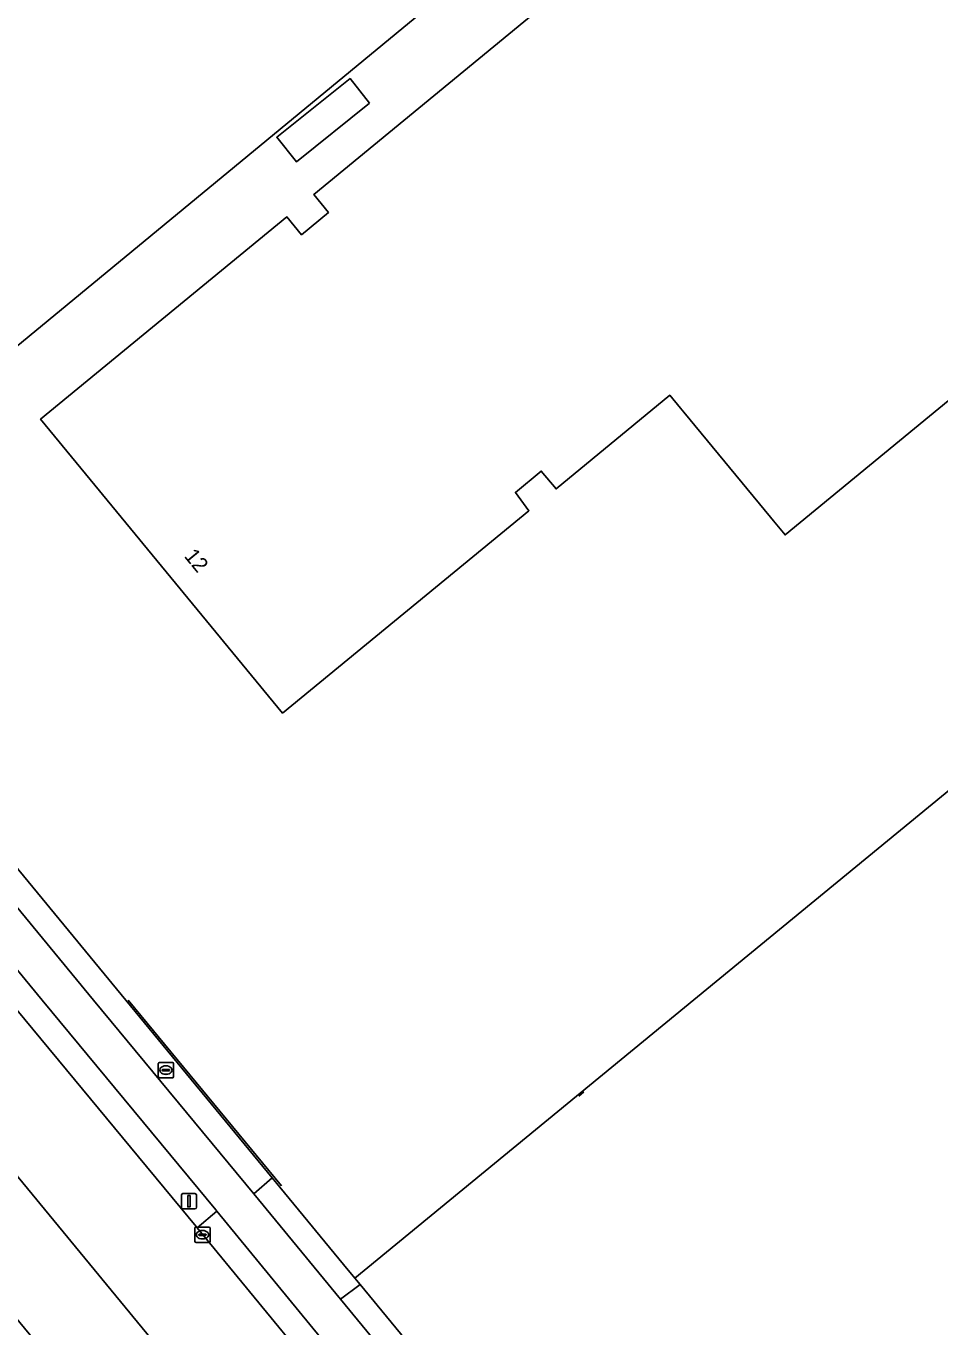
# Model space of a CAD drawing. Extents: x 156141 to 158132, y 385651 to 388333.
# Drawn here: x 157027.5 to 157087.7, y 386478.5 to 386564.1 of the extents above; entities that cross this region are included whole.
import ezdxf

# ---------------------------------------------------------------- set-up
doc = ezdxf.new("R2010")
doc.units = 0
for name, color, linetype in [('IMGEO_Berm_groen', 7, 'Continuous'), ('IMGEO_Brandkraan', 7, 'Continuous'), ('IMGEO_Erf', 7, 'Continuous'), ('IMGEO_Fietspad_gesloten', 7, 'Continuous'), ('IMGEO_Hek', 7, 'Continuous'), ('IMGEO_Kolk', 7, 'Continuous'), ('IMGEO_Lichtmast', 7, 'Continuous'), ('IMGEO_Pand', 7, 'Continuous'), ('IMGEO_Pand_nummerreeks', 7, 'Continuous'), ('IMGEO_Rijbaan_lokaal_gesloten', 7, 'Continuous'), ('IMGEO_Rijbaan_lokaal_open', 7, 'Continuous'), ('IMGEO_Voetpad_open', 7, 'Continuous')]:
    doc.layers.add(name, color=color, linetype=linetype)

msp = doc.modelspace()

# ---------------------------------------------------------------- linework, layer by layer
at = {"layer": 'IMGEO_Berm_groen'}
msp.add_lwpolyline([(157002.795, 386531.336), (157002.547, 386528.981), (157026.409, 386500), (157038.728, 386485.081), (157038.798, 386484.996), (157040.105, 386486.102), (157040.037, 386486.185), (157028.597, 386500)], close=True, dxfattribs=at)
msp.add_lwpolyline([(157002.333, 386508.861), (157009.629, 386500), (157103.143, 386386.435), (157105.1, 386384.051), (157109.728, 386387.854), (157107.759, 386390.255), (157017.392, 386500)], dxfattribs=at)
at = {"layer": 'IMGEO_Brandkraan'}
for p, q in [((157036.246, 386494.961), (157036.246, 386495.813)), ((157036.321, 386495.887), (157037.173, 386495.887)), ((157036.505, 386495.381), (157036.505, 386495.393)), ((157036.943, 386495.344), (157036.545, 386495.344)), ((157036.548, 386495.43), (157036.946, 386495.43)), ((157036.734, 386495.667), (157036.759, 386495.667)), ((157036.989, 386495.393), (157036.989, 386495.381)), ((157037.247, 386495.813), (157037.247, 386494.961)), ((157037.173, 386494.887), (157036.321, 386494.887)), ((157036.757, 386495.107), (157036.732, 386495.107))]:
    msp.add_line(p, q, dxfattribs=at)
for points in [[(157036.246, 386494.961), (157036.246, 386495.813)], [(157036.321, 386495.887), (157037.173, 386495.887)], [(157037.247, 386495.813), (157037.247, 386494.961)], [(157037.173, 386494.887), (157036.321, 386494.887)]]:
    msp.add_lwpolyline(points, dxfattribs=at)
for centre, radius, start, end in [((157036.323, 386495.811), 0.0765, 91.55205, 178.44795), ((157036.323, 386495.811), 0.0765, 91.55205, 178.44795), ((157036.545, 386495.39), 0.0403, 85.87752, 175.75265), ((157036.542, 386495.38), 0.0366, 178.93798, 274.71019), ((157036.946, 386495.387), 0.043, 264.86636, 352.45326), ((157036.95, 386495.392), 0.0386, 1.73085, 96.63898), ((157037.171, 386495.811), 0.0765, 1.55205, 88.44795), ((157037.171, 386495.811), 0.0765, 1.55205, 88.44795), ((157036.323, 386494.963), 0.0765, 181.55205, 268.44795), ((157036.323, 386494.963), 0.0765, 181.55205, 268.44795), ((157037.171, 386494.963), 0.0765, 271.55205, 358.44795), ((157037.171, 386494.963), 0.0765, 271.55205, 358.44795)]:
    msp.add_arc(centre, radius, start, end, dxfattribs=at)
for centre, major_axis, ratio, start_param, end_param in [((157036.733, 386495.387), (-0.387, 0.002), 0.722429, 4.712389, 7.853982), ((157036.758, 386495.387), (-0.39, 0.002), 0.717154, 1.570796, 4.712389)]:
    msp.add_ellipse(centre, major_axis=major_axis, ratio=ratio, start_param=start_param, end_param=end_param, dxfattribs=at)
at = {"layer": 'IMGEO_Erf'}
for points in [[(156920.91, 386652.293), (156913.636, 386646.333), (156919.699, 386638.931), (156919.907, 386638.664), (156922.955, 386634.963), (156962.332, 386587.153), (156969.416, 386578.552), (156982.109, 386563.141), (156988.377, 386555.544), (157000, 386541.408), (157034.096, 386500), (157043.743, 386488.284), (157044.247, 386487.672), (157048.737, 386482.212), (157049.528, 386481.275), (157107.842, 386410.438)], [(157151.722, 386565.874), (157139.123, 386581.228), (157135.47, 386578.262), (157123.976, 386568.812), (157130.529, 386560.852), (157115.807, 386548.732), (157109.245, 386556.702), (157077.524, 386530.624), (157076.749, 386531.562), (157076.55, 386531.804), (157070.842, 386538.714), (157070.635, 386538.981), (157069.927, 386539.821), (157062.44, 386533.651), (157061.467, 386534.832), (157059.761, 386533.43), (157060.649, 386532.218), (157044.427, 386518.897), (157028.492, 386538.247), (157044.713, 386551.57), (157045.678, 386550.395), (157047.448, 386551.867), (157046.482, 386553.041), (157111.922, 386606.864)]]:
    msp.add_lwpolyline(points, dxfattribs=at)
msp.add_lwpolyline([(157050.16, 386559.061), (157045.341, 386555.2), (157044.05, 386556.812), (157048.869, 386560.672)], close=True, dxfattribs=at)
at = {"layer": 'IMGEO_Fietspad_gesloten'}
for points in [[(156987.042, 386550.468), (156995.781, 386539.855), (157000, 386534.731), (157002.795, 386531.336), (157028.597, 386500), (157040.037, 386486.185), (157040.105, 386486.102), (157047.634, 386476.932), (157047.712, 386476.837), (157104.914, 386407.314)], [(157106.117, 386409.97), (157048.253, 386480.295), (157042.536, 386487.235), (157031.987, 386500), (157000, 386538.848)]]:
    msp.add_lwpolyline(points, dxfattribs=at)
at = {"layer": 'IMGEO_Hek'}
for points in [[(157112.507, 386613.649), (157010.32, 386529.349)], [(157151.722, 386565.874), (157049.177, 386481.677)], [(157044.352, 386487.757), (157034.269, 386500)], [(157064.266, 386493.954), (157063.939, 386493.68)]]:
    msp.add_lwpolyline(points, dxfattribs=at)
at = {"layer": 'IMGEO_Kolk'}
for p, q in [((157038.654, 386484.119), (157038.654, 386484.971)), ((157038.729, 386485.045), (157039.581, 386485.045)), ((157038.913, 386484.539), (157038.913, 386484.551)), ((157039.351, 386484.502), (157038.953, 386484.502)), ((157038.956, 386484.588), (157039.354, 386484.588)), ((157039.165, 386484.265), (157039.14, 386484.265)), ((157039.142, 386484.825), (157039.167, 386484.825)), ((157039.397, 386484.551), (157039.397, 386484.539)), ((157039.655, 386484.971), (157039.655, 386484.119)), ((157039.581, 386484.045), (157038.729, 386484.045))]:
    msp.add_line(p, q, dxfattribs=at)
for points in [[(157038.654, 386484.119), (157038.654, 386484.971)], [(157038.729, 386485.045), (157039.581, 386485.045)], [(157039.655, 386484.971), (157039.655, 386484.119)], [(157039.581, 386484.045), (157038.729, 386484.045)]]:
    msp.add_lwpolyline(points, dxfattribs=at)
for centre, radius, start, end in [((157038.731, 386484.969), 0.0765, 91.55205, 178.44795), ((157038.731, 386484.969), 0.0765, 91.55205, 178.44795), ((157038.953, 386484.548), 0.0403, 85.87752, 175.75265), ((157038.95, 386484.538), 0.0366, 178.93798, 274.71019), ((157039.354, 386484.545), 0.043, 264.86636, 352.45326), ((157039.358, 386484.55), 0.0386, 1.73085, 96.63898), ((157039.579, 386484.969), 0.0765, 1.55205, 88.44795), ((157039.579, 386484.969), 0.0765, 1.55205, 88.44795), ((157038.731, 386484.121), 0.0765, 181.55205, 268.44795), ((157038.731, 386484.121), 0.0765, 181.55205, 268.44795), ((157039.579, 386484.121), 0.0765, 271.55205, 358.44795), ((157039.579, 386484.121), 0.0765, 271.55205, 358.44795)]:
    msp.add_arc(centre, radius, start, end, dxfattribs=at)
for centre, major_axis, ratio, start_param, end_param in [((157039.141, 386484.545), (-0.387, 0.002), 0.722429, 4.712389, 7.853982), ((157039.166, 386484.545), (-0.39, 0.002), 0.717154, 1.570796, 4.712389)]:
    msp.add_ellipse(centre, major_axis=major_axis, ratio=ratio, start_param=start_param, end_param=end_param, dxfattribs=at)
at = {"layer": 'IMGEO_Lichtmast'}
for p, q in [((157037.769, 386486.353), (157037.769, 386487.153)), ((157037.769, 386487.153), (157037.769, 386486.353)), ((157037.869, 386487.253), (157038.659, 386487.253)), ((157038.659, 386487.253), (157037.869, 386487.253)), ((157038.759, 386487.153), (157038.759, 386486.353)), ((157038.759, 386486.353), (157038.759, 386487.153)), ((157038.659, 386486.253), (157037.869, 386486.253)), ((157037.869, 386486.253), (157038.659, 386486.253))]:
    msp.add_line(p, q, dxfattribs=at)
msp.add_lwpolyline([(157038.189, 386487.128), (157038.339, 386487.128), (157038.339, 386486.378), (157038.189, 386486.378), (157038.189, 386487.128)], dxfattribs=at)
for centre, start, end in [((157037.869, 386487.153), 90, 180), ((157037.869, 386487.153), 90, 180), ((157038.659, 386487.153), 0, 90), ((157038.659, 386487.153), 360, 90), ((157037.869, 386486.353), 180, 270), ((157037.869, 386486.353), 180, 270), ((157038.659, 386486.353), 270, 0), ((157038.659, 386486.353), 270, 0)]:
    msp.add_arc(centre, 0.1, start, end, dxfattribs=at)
at = {"layer": 'IMGEO_Pand'}
for points in [[(157109.245, 386556.702), (157115.807, 386548.732), (157130.529, 386560.852), (157123.976, 386568.812), (157135.47, 386578.262), (157132.44, 386581.942), (157111.922, 386606.864), (157046.482, 386553.041), (157047.448, 386551.867), (157045.678, 386550.395), (157044.713, 386551.57), (157028.492, 386538.247), (157044.427, 386518.897), (157060.649, 386532.218), (157059.761, 386533.43), (157061.467, 386534.832), (157062.44, 386533.651), (157069.927, 386539.821), (157070.635, 386538.981), (157070.842, 386538.714), (157076.55, 386531.804), (157076.749, 386531.562), (157077.524, 386530.624)], [(157050.16, 386559.061), (157048.869, 386560.672), (157044.05, 386556.812), (157045.341, 386555.2)]]:
    msp.add_lwpolyline(points, close=True, dxfattribs=at)
at = {"layer": 'IMGEO_Rijbaan_lokaal_gesloten'}
msp.add_lwpolyline([(157006.877, 386512.769), (157017.392, 386500), (157107.759, 386390.255), (157109.728, 386387.854), (157110.438, 386386.99), (157115.824, 386391.443), (157115.109, 386392.268), (157046.395, 386475.769), (157046.311, 386475.871), (157038.798, 386484.996), (157038.728, 386485.081), (157026.409, 386500), (157002.547, 386528.981), (157000, 386532.075), (156993.399, 386540.123), (156989.447, 386544.942)], dxfattribs=at)
at = {"layer": 'IMGEO_Rijbaan_lokaal_open'}
msp.add_lwpolyline([(157040.105, 386486.102), (157038.798, 386484.996), (157046.311, 386475.871), (157046.395, 386475.769), (157047.712, 386476.837), (157047.634, 386476.932)], close=True, dxfattribs=at)
at = {"layer": 'IMGEO_Voetpad_open'}
for points in [[(157043.743, 386488.284), (157034.096, 386500), (157000, 386541.408), (156988.377, 386555.544), (156987.148, 386554.494), (156991.506, 386549.164), (157000, 386538.848), (157031.987, 386500), (157042.536, 386487.235)], [(157048.737, 386482.212), (157044.247, 386487.672), (157043.743, 386488.284), (157042.536, 386487.235), (157048.253, 386480.295), (157049.528, 386481.275)]]:
    msp.add_lwpolyline(points, close=True, dxfattribs=at)
msp.add_lwpolyline([(157107.842, 386410.438), (157049.528, 386481.275), (157048.253, 386480.295), (157106.117, 386409.97)], dxfattribs=at)

# ---------------------------------------------------------------- texts
at = {"layer": 'IMGEO_Pand_nummerreeks'}
msp.add_text('12', height=1, rotation=309.46512, dxfattribs=at).set_placement((157037.901, 386529.213))

doc.saveas('drawing.dxf')
